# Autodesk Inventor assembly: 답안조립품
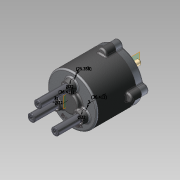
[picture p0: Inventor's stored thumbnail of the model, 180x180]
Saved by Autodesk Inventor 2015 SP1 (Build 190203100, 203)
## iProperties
Created: 2014-12
Part Number: 답안조립품
Document SubType Name: Assembly
Designer: jhkwon
Mass: 2156.77 g
Surface Area: 1801.25 cm^2
Volume: 438.523 cm^3
Density: 4.91826 g/cm^3
Author: jhkwon
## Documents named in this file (14)
- C:\Users\mypark\Desktop\Inventor1급-권준희\답안조립품.iam
- C:\Users\mypark\Desktop\Inventor1급-권준희\몸체.ipt
- C:\Users\mypark\Desktop\Inventor1급-권준희\M5x0.5x20.ipt
- C:\Users\mypark\Desktop\Inventor1급-권준희\멈춤링 10 x 1.ipt
- C:\Users\mypark\Desktop\Inventor1급-권준희\멈춤링 22 x 1.2.ipt
- C:\Users\mypark\Desktop\Inventor1급-권준희\메인 축.ipt
- C:\Users\mypark\Desktop\Inventor1급-권준희\베어링 NA 4900.ipt
- C:\Users\mypark\Desktop\Inventor1급-권준희\슬라이드 축.ipt
- C:\Users\mypark\Desktop\Inventor1급-권준희\오일실.ipt
- C:\Users\mypark\Desktop\Inventor1급-권준희\커버.ipt
- C:\Users\mypark\Desktop\Inventor1급-권준희\판캠.ipt
- C:\Users\mypark\Desktop\Inventor1급-권준희\가변스프링.ipt
- C:\Users\mypark\Desktop\Inventor1급-권준희\가변스프링2.ipt
- C:\Users\mypark\Desktop\Inventor1급-권준희\가변스프링3.ipt
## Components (7 placed, 4 different names)
1. M5x0.5x20:1
2. M5x0.5x20:2
3. M5x0.5x20:3
4. M5x0.5x20:4
5. 가변스프링:1
6. 가변스프링2:1
7. 가변스프링3:1
